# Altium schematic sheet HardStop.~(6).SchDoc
size A
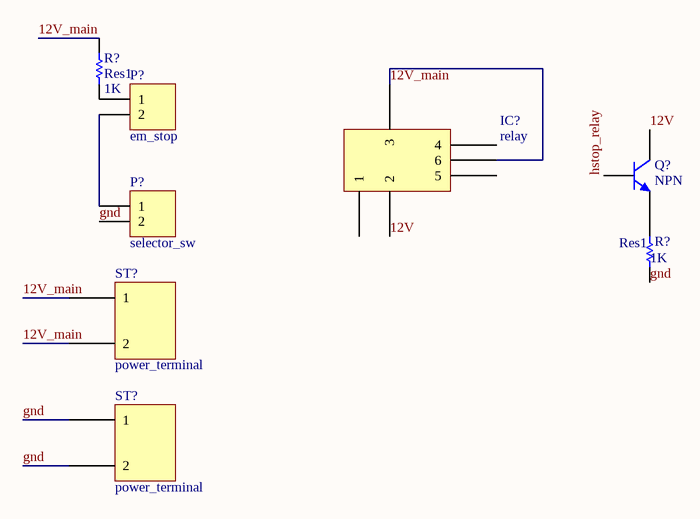
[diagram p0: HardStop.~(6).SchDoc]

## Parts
(Parts that share a designator on the sheet are numbered #1, #2 ... from top to bottom, then left to right.)
IC?  relay  [relay JQX 15F]
P?#1  em_stop  [HDR1X2H]
P?#2  selector_sw  [HDR1X2H]
Q?  NPN  [TO-226-AA]
R?#1  Res1  value 1K  [AXIAL-0.3]
R?#2  Res1  value 1K  [AXIAL-0.3]
ST?#1  power_terminal  [screw_terminal_5]
ST?#2  power_terminal  [screw_terminal_5]

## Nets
12V: IC?.2 Q?.1(C)
12V_main: IC?.3 IC?.6 R?#1.2 ST?#1.1 ST?#1.2
gnd: P?#2.2 R?#2.1 ST?#2.1 ST?#2.2
hstop_relay: Q?.2(B)
NetP?#1_1: P?#1.1 R?#1.1
NetP?#1_2: P?#1.2 P?#2.1
NetQ?_3: Q?.3(E) R?#2.2

Not connected (* = marked no-connect by the designer): IC? 1 4 5

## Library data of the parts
IC? = relay JQX-15F
P?#1 P?#2 = Header 2H: Header, 2-Pin, Right Angle
Q? = NPN: NPN Bipolar Transistor
R?#1 R?#2 = Res1: Resistor
ST?#1 ST?#2 = screw_terminal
